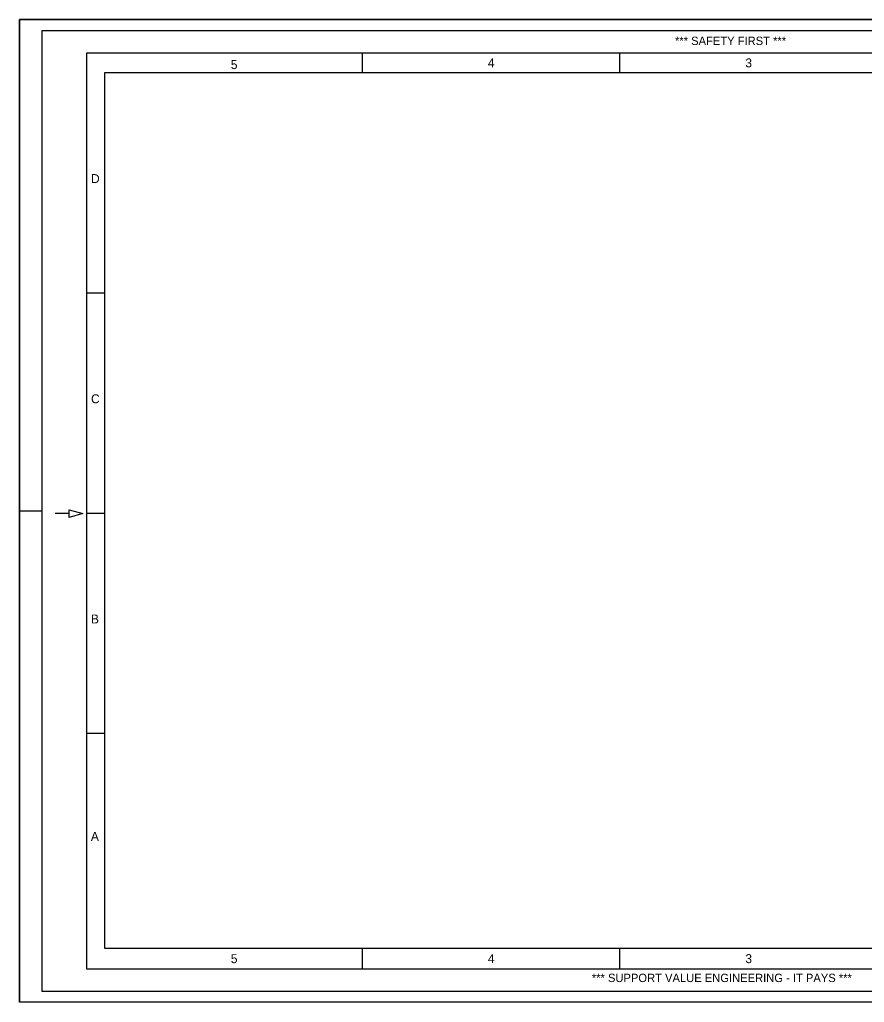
# Model space of a CAD drawing. Extents: x -0.04 to 2.79, y -0.02 to 1.81.
# Drawn here: x -0.042 to 1.534, y -0.021 to 1.813 of the extents above; entities that cross this region are included whole.
import ezdxf

# ---------------------------------------------------------------- set-up
doc = ezdxf.new("R2010")
doc.units = 0
for name, color, linetype in [('G-ANNO-NPLT', 7, 'Continuous'), ('G-ANNO-PLOT', 7, 'Continuous'), ('G-ANNO-TTLB', 7, 'Continuous')]:
    doc.layers.add(name, color=color, linetype=linetype)

msp = doc.modelspace()

# ---------------------------------------------------------------- linework, layer by layer
at = {"layer": 'G-ANNO-NPLT'}
msp.add_lwpolyline([(-0.0417, 1.8125), (2.7917, 1.8125), (2.7917, -0.0208), (-0.0417, -0.0208)], close=True, dxfattribs=at)
at = {"layer": 'G-ANNO-PLOT'}
for p, q in [((2.7917, 1.8125), (-0.0417, 1.8125)), ((-0.0417, 1.8125), (-0.0417, -0.0208)), ((0, 0.8958), (-0.0417, 0.8958)), ((2.7917, -0.0208), (-0.0417, -0.0208))]:
    msp.add_line(p, q, dxfattribs=at)
msp.add_lwpolyline([(0, 0), (2.7917, 0), (2.7917, 1.7917), (0, 1.7917)], close=True, dxfattribs=at)
at = {"layer": 'G-ANNO-TTLB'}
for p, q in [((0.5978, 1.7131), (0.5978, 1.75)), ((1.0778, 1.7131), (1.0778, 1.75)), ((0.1166, 1.3022), (0.0833, 1.3022)), ((0.0506, 0.891), (0.0246, 0.891)), ((0.1166, 0.8914), (0.0833, 0.8914)), ((0.1166, 0.4806), (0.0833, 0.4806)), ((0.5978, 0.0418), (0.5978, 0.0803)), ((1.0778, 0.0418), (1.0778, 0.0803)), ((0.0833, 0.0417), (0.0833, 0.0417))]:
    msp.add_line(p, q, dxfattribs=at)
for points in [[(0.2515, 1.75), (0.0833, 1.75), (0.0833, 0.0417)], [(0.0833, 0.0417), (2.7292, 0.0417), (2.7292, 1.75), (0.2515, 1.75)], [(0.1166, 0.0803), (2.695, 0.0803), (2.695, 1.7131), (0.1166, 1.7131)], [(0.1166, 1.7131), (0.1166, 0.0803)]]:
    msp.add_lwpolyline(points, dxfattribs=at)
msp.add_lwpolyline([(0.0506, 0.8983), (0.0765, 0.891), (0.0506, 0.8837)], close=True, dxfattribs=at)

# ---------------------------------------------------------------- texts
for s, height, p in [('*** SAFETY FIRST ***', 0.015583, (1.181, 1.7652)), ('5', 0.0167, (0.3523, 1.7203)), ('4', 0.0167, (0.8319, 1.7235)), ('3', 0.0167, (1.3123, 1.7235)), ('D', 0.0167, (0.0915, 1.5076)), ('C', 0.0167, (0.0915, 1.0968)), ('B', 0.0167, (0.0914, 0.686)), ('A', 0.0167, (0.0912, 0.2804)), ('5', 0.0167, (0.3523, 0.0523)), ('4', 0.0167, (0.8319, 0.0523)), ('3', 0.0167, (1.3123, 0.0523)), ('*** SUPPORT VALUE ENGINEERING - IT PAYS ***', 0.015583, (1.0258, 0.017))]:
    msp.add_text(s, height=height, dxfattribs=at).set_placement(p)

doc.saveas('drawing.dxf')
